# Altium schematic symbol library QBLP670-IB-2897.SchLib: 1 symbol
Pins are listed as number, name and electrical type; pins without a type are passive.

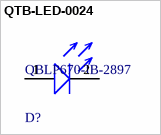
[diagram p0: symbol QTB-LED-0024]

## QTB-LED-0024
designator D?, comment QBLP670-IB-2897
LED BLUE CLEAR 2PLCC SMD; Manufacturer: QT Brightek (QTB); Luminous Intensity: 300mcd; Test Current: 20mA; Lens Color: Colorless; Lens Style: Oval with Flat Top; Forward Voltage: 3.1V; Wavelength - Dominant: 470nm; Viewing Angle: 120°
footprint QBLP670-IB-2897
pins: 1 ANODE (+), 2 CATHODE (-)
